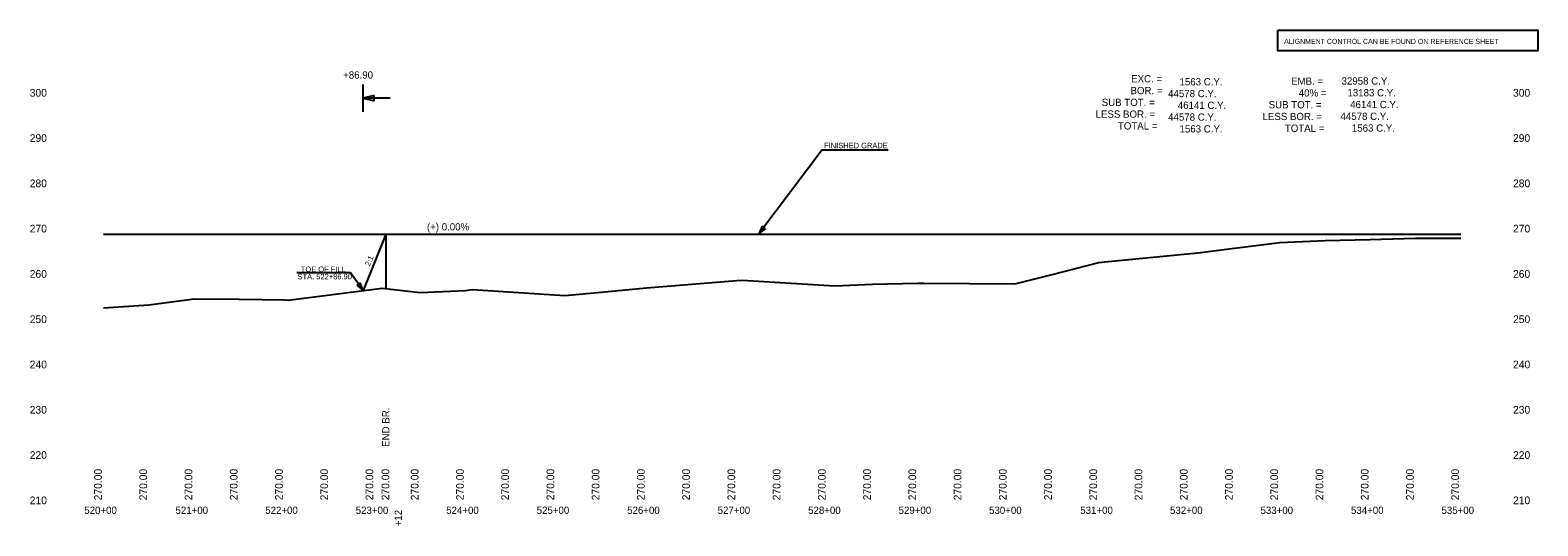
# Model space of a CAD drawing. Extents: x 49105 to 50775, y 45514 to 53458.
# Drawn here: x 49107 to 50773, y 48951 to 49498 of the extents above; entities that cross this region are included whole.
import ezdxf

# ---------------------------------------------------------------- set-up
doc = ezdxf.new("R2010")
doc.units = 0
for name, color, linetype in [('Level 1', 7, 'Continuous'), ('Level 24', 7, 'Continuous'), ('Level 25', 7, 'Continuous'), ('Level 40', 7, 'Continuous'), ('Level 41', 7, 'Continuous'), ('Level 42', 7, 'Continuous'), ('Level 43', 7, 'Continuous'), ('Level 45', 7, 'Continuous')]:
    doc.layers.add(name, color=color, linetype=linetype)

msp = doc.modelspace()

# ---------------------------------------------------------------- linework, layer by layer
at = {"layer": 'Level 1'}
for p, q in [((49474.8, 49407.9), (49474.8, 49437.9)), ((49504.8, 49422.9), (49474.8, 49422.9)), ((49982.1, 49366), (49912.3, 49273)), ((49982.1, 49366), (50054.9, 49366))]:
    msp.add_line(p, q, dxfattribs=at)
at = {"layer": 'Level 24'}
for p, q in [((49486.8, 49425.9), (49474.8, 49422.9)), ((49486.8, 49419.9), (49486.8, 49425.9)), ((49474.8, 49422.9), (49486.8, 49419.9)), ((49915.9, 49281.5), (49912.3, 49273)), ((49912.3, 49273), (49919.5, 49278.8)), ((49919.5, 49278.8), (49915.9, 49281.5)), ((49471.4, 49219.1), (49467.8, 49216.5)), ((49467.8, 49216.5), (49474.8, 49210.4)), ((49474.8, 49210.4), (49471.4, 49219.1))]:
    msp.add_line(p, q, dxfattribs=at)
at = {"layer": 'Level 25'}
msp.add_lwpolyline([(50485.8, 49498), (50773.1, 49498), (50773.1, 49475.2), (50485.8, 49475.2)], close=True, dxfattribs=at)
at = {"layer": 'Level 40'}
msp.add_lwpolyline([(49187.9, 49191.5), (49237.9, 49194.9), (49287.9, 49201.4), (49337.9, 49200.9), (49387.9, 49200.1), (49391.8, 49200), (49495.7, 49213), (49537.9, 49208.2), (49587.9, 49210.7), (49595.6, 49211.5), (49697.6, 49205.2), (49737.9, 49208.8), (49787.9, 49213.5), (49837.9, 49217.7), (49887.9, 49221.7), (49893.7, 49222.1), (49996.2, 49215.7), (50037.9, 49217.5), (50087.9, 49218.6), (50094.3, 49218.8), (50194.9, 49217.8), (50237.9, 49228.7), (50287.9, 49241.5), (50294.6, 49242.2), (50397.5, 49252.1), (50437.9, 49257.2), (50487.9, 49263.5), (50537.9, 49265.7), (50587.9, 49266.8), (50637.9, 49268.4), (50687.9, 49268.4)], dxfattribs=at)
at = {"layer": 'Level 45'}
for p, q in [((49187.9, 49272.9), (49499.9, 49272.9)), ((49499.9, 49272.9), (49474.8, 49210.4)), ((49499.9, 49272.9), (49499.9, 49212.5)), ((49499.9, 49272.9), (50687.9, 49272.9)), ((49460.8, 49230.2), (49401.4, 49230.2)), ((49474.8, 49210.4), (49460.8, 49230.2))]:
    msp.add_line(p, q, dxfattribs=at)

# ---------------------------------------------------------------- texts
at = {"layer": 'Level 1'}
for s, height, p in [('+86.90', 8, (49452.7, 49444.5)), ('EXC. =', 8, (50323.6, 49440.3)), (' 1563 C.Y.', 8, (50374.1, 49437)), ('EMB. = ', 8, (50500.4, 49437.7)), (' 32958 C.Y.', 8, (50553.2, 49437.9)), ('BOR. =', 8, (50322.9, 49427.3)), (' 44578 C.Y.', 8, (50361.5, 49424)), ('40% =', 8, (50508.9, 49424.7)), (' 13183 C.Y.', 8, (50559.7, 49424.9)), ('LESS BOR. =', 8, (50284.3, 49401.3)), ('SUB TOT. =', 8, (50291.1, 49414.3)), (' 46141 C.Y.', 8, (50372.2, 49411)), ('SUB TOT. =', 8, (50475.6, 49411.7)), (' 46141 C.Y.', 8, (50562.7, 49411.9)), ('TOTAL =', 8, (50309, 49388.3)), (' 44578 C.Y.', 8, (50361.5, 49398)), (' 1563 C.Y.', 8, (50374.1, 49385)), ('LESS BOR. =', 8, (50468.8, 49398.7)), ('TOTAL =', 8, (50493.5, 49385.7)), (' 44578 C.Y.', 8, (50552, 49398.9)), (' 1563 C.Y.', 8, (50564.6, 49385.9)), ('FINISHED GRADE', 6, (49984.2, 49367.6))]:
    msp.add_text(s, height=height, dxfattribs=at).set_placement(p)
at = {"layer": 'Level 25'}
msp.add_text('ALIGNMENT CONTROL CAN BE FOUND ON REFERENCE SHEET', height=5.6, dxfattribs=at).set_placement((50492.7, 49482.8))
at = {"layer": 'Level 41'}
msp.add_text('(+) 0.00%', height=8, dxfattribs=at).set_placement((49545.3, 49276.9))
at = {"layer": 'Level 42'}
for s, height, p in [('300', 8.5, (49106.3, 49424.6)), ('300', 8.5, (50745.7, 49424.6)), ('290', 8.5, (49106.3, 49374.6)), ('290', 8.5, (50745.7, 49374.6)), ('280', 8.5, (49106.3, 49324.6)), ('280', 8.5, (50745.7, 49324.6)), ('270', 8.5, (49106.3, 49274.6)), ('270', 8.5, (50745.7, 49274.6)), ('260', 8.5, (49106.3, 49224.6)), ('260', 8.5, (50745.7, 49224.6)), ('250', 8.5, (49106.3, 49174.6)), ('250', 8.5, (50745.7, 49174.6)), ('240', 8.5, (49106.3, 49124.6)), ('240', 8.5, (50745.7, 49124.6)), ('230', 8.5, (49106.3, 49074.6)), ('230', 8.5, (50745.7, 49074.6)), ('220', 8.5, (49106.3, 49024.6)), ('220', 8.5, (50745.7, 49024.6)), ('210', 8.5, (49106.3, 48974.6)), ('210', 8.5, (50745.7, 48974.6)), ('520+00', 8, (49166.6, 48963.9)), ('521+00', 8, (49267.4, 48963.9)), ('522+00', 8, (49366.6, 48963.9)), ('523+00', 8, (49466.6, 48963.9)), ('524+00', 8, (49566.6, 48963.9)), ('525+00', 8, (49666.6, 48963.9)), ('526+00', 8, (49766.6, 48963.9)), ('527+00', 8, (49866.6, 48963.9)), ('528+00', 8, (49966.6, 48963.9)), ('529+00', 8, (50066.6, 48963.9)), ('530+00', 8, (50166.6, 48963.9)), ('531+00', 8, (50267.4, 48963.9)), ('532+00', 8, (50366.6, 48963.9)), ('533+00', 8, (50466.6, 48963.9)), ('534+00', 8, (50566.6, 48963.9)), ('535+00', 8, (50666.6, 48963.9))]:
    msp.add_text(s, height=height, dxfattribs=at).set_placement(p)
for s, p in [('END BR.', (49503.8, 49037.9)), ('+12', (49517.6, 48950.2))]:
    msp.add_text(s, height=8, rotation=90, dxfattribs=at).set_placement(p)
at = {"layer": 'Level 43'}
for p in [(49186, 48978.9), (49236, 48978.9), (49286, 48978.9), (49336, 48978.9), (49386, 48978.9), (49436, 48978.9), (49486, 48978.9), (49503.7, 48978.9), (49536, 48978.9), (49586, 48978.9), (49636, 48978.9), (49686, 48978.9), (49736, 48978.9), (49786, 48978.9), (49836, 48978.9), (49886, 48978.9), (49936, 48978.9), (49986, 48978.9), (50036, 48978.9), (50086, 48978.9), (50136, 48978.9), (50186, 48978.9), (50236, 48978.9), (50286, 48978.9), (50336, 48978.9), (50386, 48978.9), (50436, 48978.9), (50486, 48978.9), (50536, 48978.9), (50586, 48978.9), (50636, 48978.9), (50686, 48978.9)]:
    msp.add_text('270.00', height=8.5, rotation=90, dxfattribs=at).set_placement(p)
at = {"layer": 'Level 45'}
msp.add_text('2:1', height=6, rotation=68.0994, dxfattribs=at).set_placement((49482.2, 49236.9))
for s, p in [('STA. 522+86.90', (49402.3, 49222.9)), ('TOE OF FILL ', (49405.9, 49231))]:
    msp.add_text(s, height=6, dxfattribs=at).set_placement(p)

doc.saveas('drawing.dxf')
